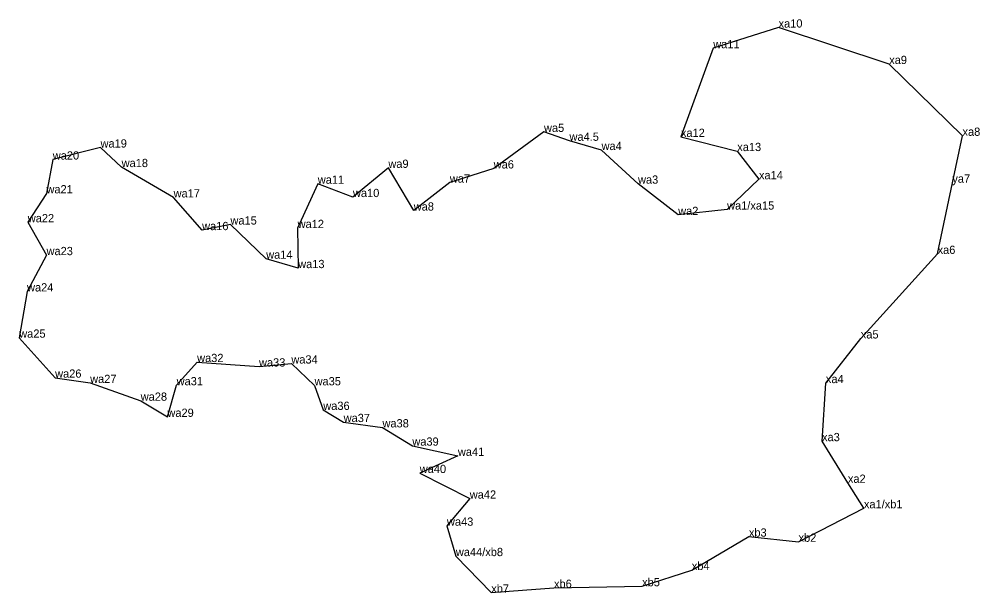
# Model space of a CAD drawing. Extents: x 2072529 to 2267990, y 436423 to 470008.
# Drawn here: x 2212593 to 2213292, y 439094 to 439511 of the extents above; entities that cross this region are included whole.
import ezdxf

# ---------------------------------------------------------------- set-up
doc = ezdxf.new("R2010")
doc.units = 0
doc.layers.add('Level 3', color=7, linetype='Continuous')
doc.layers.add('Old_Level_52', color=7, linetype='Continuous')

msp = doc.modelspace()

# ---------------------------------------------------------------- linework, layer by layer
at = {"layer": 'Level 3'}
for p, q in [((2213145.724, 439505.268), (2213145.724, 439505.268)), ((2213098.165, 439490.206), (2213098.165, 439490.206)), ((2213226.286, 439478.733), (2213226.286, 439478.733)), ((2212974.922, 439429.332), (2212974.922, 439429.332)), ((2212993.493, 439422.841), (2212993.493, 439422.841)), ((2213074.626, 439425.687), (2213074.626, 439425.687)), ((2213279.661, 439426.478), (2213279.661, 439426.478)), ((2212652.005, 439417.952), (2212652.005, 439417.952)), ((2213016.836, 439416.114), (2213016.836, 439416.114)), ((2212617.223, 439409.186), (2212617.223, 439409.186)), ((2213115.628, 439415.371), (2213115.628, 439415.371)), ((2212667.386, 439403.708), (2212667.386, 439403.708)), ((2212861.592, 439403.165), (2212861.592, 439403.165)), ((2212938.311, 439402.695), (2212938.311, 439402.695)), ((2213131.462, 439394.858), (2213131.462, 439394.858)), ((2212810.197, 439391.588), (2212810.197, 439391.588)), ((2212906.365, 439392.432), (2212906.365, 439392.432)), ((2213043.382, 439391.638), (2213043.382, 439391.638)), ((2213272.272, 439392.325), (2213272.272, 439392.325)), ((2212612.628, 439384.585), (2212612.628, 439384.585)), ((2212705.223, 439381.627), (2212705.223, 439381.627)), ((2212835.821, 439381.897), (2212835.821, 439381.897)), ((2212880.063, 439372.049), (2212880.063, 439372.049)), ((2213072.624, 439368.847), (2213072.624, 439368.847)), ((2213108.255, 439372.761), (2213108.255, 439372.761)), ((2212599.026, 439363.561), (2212599.026, 439363.561)), ((2212746.593, 439361.894), (2212746.593, 439361.894)), ((2212725.974, 439357.826), (2212725.974, 439357.826)), ((2212795.538, 439359.331), (2212795.538, 439359.331)), ((2212612.695, 439339.618), (2212612.695, 439339.618)), ((2213261.53, 439340.505), (2213261.53, 439340.505)), ((2212772.649, 439337), (2212772.649, 439337)), ((2212795.916, 439330.172), (2212795.916, 439330.172)), ((2212598.493, 439313.182), (2212598.493, 439313.182)), ((2212592.81, 439279.509), (2212592.81, 439279.509)), ((2213205.596, 439278.952), (2213205.596, 439278.952)), ((2212722.335, 439261.789), (2212722.335, 439261.789)), ((2212767.405, 439258.553), (2212767.405, 439258.553)), ((2212790.955, 439260.71), (2212790.955, 439260.71)), ((2212618.931, 439250.411), (2212618.931, 439250.411)), ((2212644.44, 439246.564), (2212644.44, 439246.564)), ((2212707.426, 439244.876), (2212707.426, 439244.876)), ((2212807.867, 439244.822), (2212807.867, 439244.822)), ((2213180.188, 439246.47), (2213180.188, 439246.47)), ((2212681.269, 439233.617), (2212681.269, 439233.617)), ((2212814.216, 439226.959), (2212814.216, 439226.959)), ((2212700.696, 439221.894), (2212700.696, 439221.894)), ((2212829.038, 439218.104), (2212829.038, 439218.104)), ((2212857.31, 439214.224), (2212857.31, 439214.224)), ((2212879.069, 439200.93), (2212879.069, 439200.93)), ((2213177.392, 439204.203), (2213177.392, 439204.203)), ((2212912.243, 439193.51), (2212912.243, 439193.51)), ((2212884.45, 439181.025), (2212884.45, 439181.025)), ((2213196.206, 439173.906), (2213196.206, 439173.906)), ((2212920.862, 439162.37), (2212920.862, 439162.37)), ((2213207.869, 439155.37), (2213207.869, 439155.37)), ((2212904.263, 439142.656), (2212904.263, 439142.656)), ((2213124.116, 439134.722), (2213124.116, 439134.722)), ((2213160.293, 439130.979), (2213160.293, 439130.979)), ((2212910.749, 439120.535), (2212910.749, 439120.535)), ((2213082.517, 439110.411), (2213082.517, 439110.411)), ((2212936.536, 439093.932), (2212936.536, 439093.932)), ((2212982.206, 439097.383), (2212982.206, 439097.383)), ((2213046.357, 439098.584), (2213046.357, 439098.584))]:
    msp.add_line(p, q, dxfattribs=at)
at = {"layer": 'Old_Level_52'}
msp.add_lwpolyline([(2213207.869, 439155.37), (2213196.206, 439173.906), (2213177.392, 439204.203), (2213180.188, 439246.47), (2213205.596, 439278.952), (2213261.53, 439340.505), (2213272.272, 439392.325), (2213279.661, 439426.478), (2213226.286, 439478.733), (2213145.724, 439505.268), (2213098.165, 439490.206), (2213074.626, 439425.687), (2213115.628, 439415.371), (2213131.462, 439394.858), (2213108.255, 439372.761), (2213072.624, 439368.847), (2213043.382, 439391.638), (2213016.836, 439416.114), (2212993.493, 439422.841), (2212974.922, 439429.332), (2212938.311, 439402.695), (2212906.365, 439392.432), (2212880.063, 439372.049), (2212861.592, 439403.165), (2212835.821, 439381.897), (2212810.197, 439391.588), (2212795.538, 439359.331), (2212795.916, 439330.172), (2212772.649, 439337), (2212746.593, 439361.894), (2212725.974, 439357.826), (2212705.223, 439381.627), (2212667.386, 439403.708), (2212652.005, 439417.952), (2212617.223, 439409.186), (2212612.628, 439384.585), (2212599.026, 439363.561), (2212612.695, 439339.618), (2212598.493, 439313.182), (2212592.81, 439279.509), (2212618.931, 439250.411), (2212644.44, 439246.564), (2212681.269, 439233.617), (2212700.696, 439221.894), (2212707.426, 439244.876), (2212722.335, 439261.789), (2212767.405, 439258.553), (2212790.955, 439260.71), (2212807.867, 439244.822), (2212814.216, 439226.959), (2212829.038, 439218.104), (2212857.31, 439214.224), (2212879.069, 439200.93), (2212912.243, 439193.51), (2212884.45, 439181.025), (2212920.862, 439162.37), (2212904.263, 439142.656), (2212910.749, 439120.535), (2212936.536, 439093.932), (2212982.206, 439097.383), (2213046.357, 439098.584), (2213082.517, 439110.411), (2213124.116, 439134.722), (2213160.293, 439130.979)], close=True, dxfattribs=at)

# ---------------------------------------------------------------- texts
for s, p in [('xa10', (2213145.724, 439505.268)), ('wa11', (2213098.165, 439490.206)), ('xa9', (2213226.286, 439478.733)), ('wa5', (2212974.922, 439429.332)), ('xa12', (2213074.626, 439425.687)), ('xa8', (2213279.661, 439426.478)), ('wa19', (2212652.005, 439417.952)), ('wa4.5', (2212993.493, 439422.841)), ('wa4', (2213016.836, 439416.114)), ('xa13', (2213115.628, 439415.371)), ('wa20', (2212617.223, 439409.186)), ('wa18', (2212667.386, 439403.708)), ('wa9', (2212861.592, 439403.165)), ('wa6', (2212938.311, 439402.695)), ('wa11', (2212810.197, 439391.588)), ('wa7', (2212906.365, 439392.432)), ('wa3', (2213043.382, 439391.638)), ('xa14', (2213131.462, 439394.858)), ('ya7', (2213272.272, 439392.325)), ('wa21', (2212612.628, 439384.585)), ('wa10', (2212835.821, 439381.897)), ('wa17', (2212705.223, 439381.627)), ('wa8', (2212880.063, 439372.049)), ('wa2', (2213072.624, 439368.847)), ('wa1/xa15', (2213108.255, 439372.761)), ('wa22', (2212599.026, 439363.561)), ('wa15', (2212746.593, 439361.894)), ('wa16', (2212725.974, 439357.826)), ('wa12', (2212795.538, 439359.331)), ('wa23', (2212612.695, 439339.618)), ('xa6', (2213261.53, 439340.505)), ('wa14', (2212772.649, 439337)), ('wa13', (2212795.916, 439330.172)), ('wa24', (2212598.493, 439313.182)), ('wa25', (2212592.81, 439279.509)), ('xa5', (2213205.596, 439278.952)), ('wa32', (2212722.335, 439261.789)), ('wa33', (2212767.405, 439258.553)), ('wa34', (2212790.955, 439260.71)), ('wa26', (2212618.931, 439250.411)), ('wa27', (2212644.44, 439246.564)), ('wa31', (2212707.426, 439244.876)), ('wa35', (2212807.867, 439244.822)), ('xa4', (2213180.188, 439246.47)), ('wa28', (2212681.269, 439233.617)), ('wa29', (2212700.696, 439221.894)), ('wa36', (2212814.216, 439226.959)), ('wa37', (2212829.038, 439218.104)), ('wa38', (2212857.31, 439214.224)), ('wa39', (2212879.069, 439200.93)), ('xa3', (2213177.392, 439204.203)), ('wa41', (2212912.243, 439193.51)), ('wa40', (2212884.45, 439181.025)), ('xa2', (2213196.206, 439173.906)), ('wa42', (2212920.862, 439162.37)), ('xa1/xb1', (2213207.869, 439155.37)), ('wa43', (2212904.263, 439142.656)), ('xb3', (2213124.116, 439134.722)), ('xb2', (2213160.293, 439130.979)), ('wa44/xb8', (2212910.749, 439120.535)), ('xb4', (2213082.517, 439110.411)), ('xb6', (2212982.206, 439097.383)), ('xb5', (2213046.357, 439098.584)), ('xb7', (2212936.536, 439093.932))]:
    msp.add_text(s, height=6).set_placement(p)

doc.saveas('drawing.dxf')
